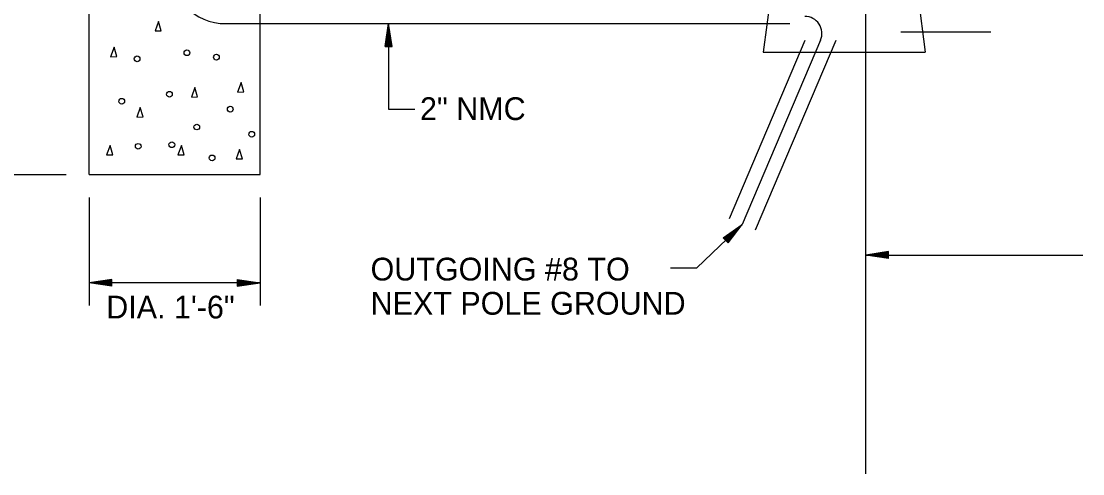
# Model space of a CAD drawing. Extents: x 1370140 to 1371141, y 380020 to 380660.
# Drawn here: x 1370273.3 to 1370506.2, y 380292.1 to 380391.4 of the extents above; entities that cross this region are included whole.
import ezdxf

# ---------------------------------------------------------------- set-up
doc = ezdxf.new("R2010")
doc.units = 0
doc.layers.add('R_Draft', color=7, linetype='Continuous')

msp = doc.modelspace()

# ---------------------------------------------------------------- linework, layer by layer
at = {"layer": 'R_Draft'}
for p, q in [((1370288.22, 380357.73), (1370288.22, 380432.73)), ((1370325.72, 380357.73), (1370325.72, 380432.73)), ((1370442.35, 380432.73), (1370436.1, 380384.59)), ((1370465.35, 380432.73), (1370471.6, 380384.59)), ((1370458.55, 380292.09), (1370458.55, 380419.6)), ((1370318.22, 380390.84), (1370441.9, 380390.84)), ((1370353.16, 380385.84), (1370353.91, 380390.84)), ((1370353.29, 380385.84), (1370353.91, 380390)), ((1370353.91, 380390.84), (1370353.91, 380372.05)), ((1370354.66, 380385.84), (1370353.91, 380390.84)), ((1370354.54, 380385.84), (1370353.91, 380390)), ((1370353.41, 380385.84), (1370353.91, 380389.14)), ((1370353.54, 380385.84), (1370353.91, 380388.31)), ((1370354.41, 380385.84), (1370353.91, 380389.14)), ((1370354.28, 380385.84), (1370353.91, 380388.31)), ((1370466.24, 380389.07), (1370486.02, 380389.07)), ((1370353.16, 380385.84), (1370354.66, 380385.84)), ((1370353.67, 380385.84), (1370353.91, 380387.46)), ((1370353.79, 380385.84), (1370353.91, 380386.63)), ((1370354.16, 380385.84), (1370353.91, 380387.46)), ((1370354.03, 380385.84), (1370353.91, 380386.63)), ((1370445.21, 380387.13), (1370428.59, 380348)), ((1370448.65, 380387.23), (1370431.47, 380346.78)), ((1370452, 380387.13), (1370434.34, 380345.56)), ((1370436.1, 380384.59), (1370471.6, 380384.59)), ((1370353.91, 380372.05), (1370359.67, 380372.05)), ((1370241.03, 380357.73), (1370283.22, 380357.73)), ((1370288.22, 380357.73), (1370325.72, 380357.73)), ((1370288.22, 380352.73), (1370288.22, 380328.98)), ((1370325.72, 380352.73), (1370325.72, 380328.98)), ((1370431.47, 380346.78), (1370421.51, 380337.29)), ((1370427.33, 380343.87), (1370431.47, 380346.78)), ((1370427.42, 380343.78), (1370430.86, 380346.21)), ((1370428.28, 380342.88), (1370430.86, 380346.21)), ((1370428.37, 380342.79), (1370431.47, 380346.78)), ((1370427.33, 380343.87), (1370428.37, 380342.79)), ((1370427.5, 380343.69), (1370430.24, 380345.61)), ((1370427.59, 380343.6), (1370429.64, 380345.04)), ((1370427.68, 380343.51), (1370429.02, 380344.45)), ((1370427.77, 380343.42), (1370428.42, 380343.88)), ((1370427.93, 380343.25), (1370428.42, 380343.88)), ((1370428.02, 380343.15), (1370429.02, 380344.45)), ((1370428.1, 380343.06), (1370429.64, 380345.04)), ((1370428.19, 380342.97), (1370430.24, 380345.61)), ((1370463.55, 380340.82), (1370458.55, 380340.07)), ((1370458.55, 380340.07), (1370506.17, 380340.07)), ((1370463.55, 380339.32), (1370458.55, 380340.07)), ((1370463.55, 380340.69), (1370459.38, 380340.07)), ((1370463.55, 380339.44), (1370459.38, 380340.07)), ((1370463.55, 380340.56), (1370460.24, 380340.07)), ((1370463.55, 380339.57), (1370460.24, 380340.07)), ((1370463.55, 380340.44), (1370461.08, 380340.07)), ((1370463.55, 380339.69), (1370461.08, 380340.07)), ((1370463.55, 380340.31), (1370461.92, 380340.07)), ((1370463.55, 380339.82), (1370461.92, 380340.07)), ((1370463.55, 380340.18), (1370462.76, 380340.07)), ((1370463.55, 380339.95), (1370462.76, 380340.07)), ((1370463.55, 380339.32), (1370463.55, 380340.82)), ((1370415.75, 380337.29), (1370421.51, 380337.29)), ((1370293.22, 380334.73), (1370288.22, 380333.98)), ((1370293.22, 380334.61), (1370289.06, 380333.98)), ((1370293.22, 380334.48), (1370289.92, 380333.98)), ((1370293.22, 380334.36), (1370290.75, 380333.98)), ((1370293.22, 380334.23), (1370291.6, 380333.98)), ((1370293.22, 380334.1), (1370292.43, 380333.98)), ((1370293.22, 380333.23), (1370293.22, 380334.73)), ((1370320.72, 380334.73), (1370325.72, 380333.98)), ((1370320.72, 380334.73), (1370320.72, 380333.23)), ((1370320.72, 380334.61), (1370324.89, 380333.98)), ((1370320.72, 380334.48), (1370324.03, 380333.98)), ((1370320.72, 380334.36), (1370323.19, 380333.98)), ((1370320.72, 380334.23), (1370322.35, 380333.98)), ((1370320.72, 380334.1), (1370321.51, 380333.98)), ((1370325.72, 380333.98), (1370288.22, 380333.98)), ((1370293.22, 380333.23), (1370288.22, 380333.98)), ((1370293.22, 380333.36), (1370289.06, 380333.98)), ((1370293.22, 380333.49), (1370289.92, 380333.98)), ((1370293.22, 380333.61), (1370290.75, 380333.98)), ((1370293.22, 380333.74), (1370291.6, 380333.98)), ((1370293.22, 380333.87), (1370292.43, 380333.98)), ((1370320.72, 380333.23), (1370325.72, 380333.98)), ((1370320.72, 380333.74), (1370322.35, 380333.98)), ((1370320.72, 380333.49), (1370324.03, 380333.98)), ((1370320.72, 380333.36), (1370324.89, 380333.98)), ((1370320.72, 380333.61), (1370323.19, 380333.98)), ((1370320.72, 380333.87), (1370321.51, 380333.98))]:
    msp.add_line(p, q, dxfattribs=at)
for points in [[(1370303.44, 380391.3), (1370302.68, 380389.23), (1370304.06, 380389.29), (1370303.44, 380391.3)], [(1370293.7, 380385.66), (1370292.94, 380383.58), (1370294.32, 380383.64), (1370293.7, 380385.66)], [(1370311.41, 380376.8), (1370310.66, 380374.72), (1370312.03, 380374.78), (1370311.41, 380376.8)], [(1370321.55, 380377.91), (1370320.79, 380375.84), (1370322.17, 380375.9), (1370321.55, 380377.91)], [(1370299.44, 380372.41), (1370298.69, 380370.33), (1370300.06, 380370.39), (1370299.44, 380372.41)], [(1370292.82, 380364.1), (1370292.06, 380362.03), (1370293.44, 380362.08), (1370292.82, 380364.1)], [(1370308.46, 380364.1), (1370307.71, 380362.03), (1370309.08, 380362.08), (1370308.46, 380364.1)], [(1370321.23, 380363.22), (1370320.47, 380361.15), (1370321.85, 380361.2), (1370321.23, 380363.22)]]:
    msp.add_lwpolyline(points, dxfattribs=at)
for centre in [(1370298.76, 380383.12), (1370309.68, 380384.45), (1370316.15, 380383.49), (1370305.85, 380375.35), (1370295.38, 380373.81), (1370319.18, 380372.08), (1370311.84, 380368.16), (1370323.89, 380366.57), (1370298.99, 380363.93), (1370306.37, 380364.27), (1370315.19, 380361.38)]:
    msp.add_circle(centre, 0.625, dxfattribs=at)
for centre, radius, start, end in [((1370318.22, 380403.34), 12.5, 180, 270), ((1370445.2, 380388.69), 3.75, 336.984, 90)]:
    msp.add_arc(centre, radius, start, end, dxfattribs=at)

# ---------------------------------------------------------------- texts
for s, p in [('2" NMC', (1370360.8, 380369.69)), ('OUTGOING #8 TO', (1370349.96, 380334.49)), ('NEXT POLE GROUND', (1370349.96, 380326.99)), ('DIA. 1\'-6"', (1370291.98, 380326.16))]:
    msp.add_text(s, height=5, dxfattribs=at).set_placement(p)

doc.saveas('drawing.dxf')
